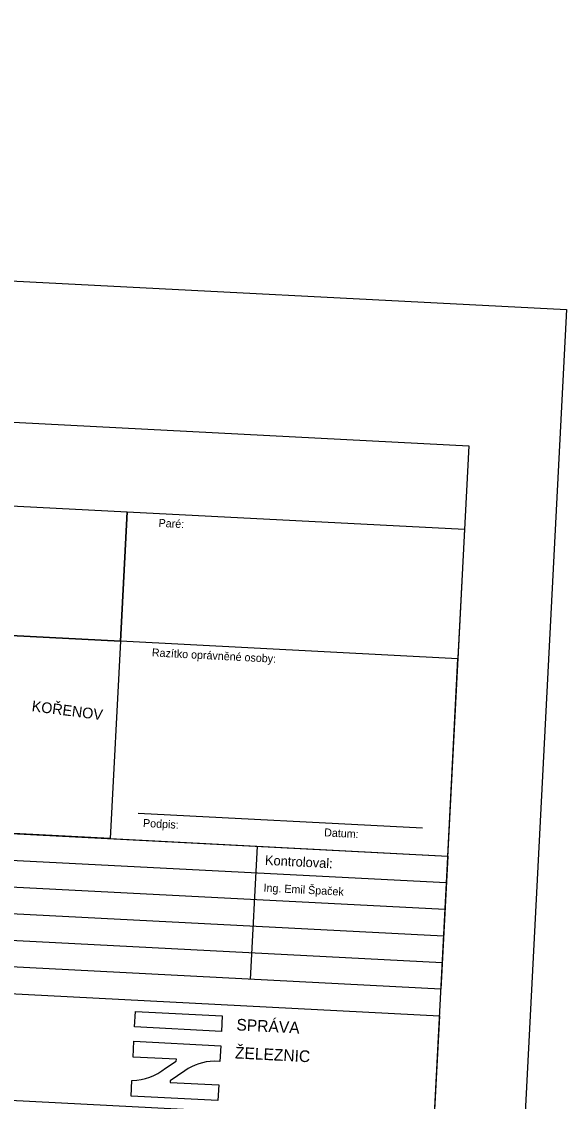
# Model space of a CAD drawing. Extents: x -669661 to -669105, y -977202 to -977030.
# Drawn here: x -669155.8 to -669104.7, y -977131.5 to -977030.3 of the extents above; entities that cross this region are included whole.
import ezdxf

# ---------------------------------------------------------------- set-up
doc = ezdxf.new("R2010")
doc.units = 0
doc.layers.add('ROZPISKA', color=7, linetype='Continuous')
doc.layers.add('Schéma', color=7, linetype='Continuous')

msp = doc.modelspace()

# ---------------------------------------------------------------- linework, layer by layer
at = {"layer": 'Defpoints'}
for p, q in [((-669629.05, -977030.28), (-669104.74, -977057.27)), ((-669629.05, -977030.28), (-669104.74, -977057.27)), ((-669104.74, -977057.27), (-669112.17, -977201.58)), ((-669104.74, -977057.27), (-669112.17, -977201.58))]:
    msp.add_line(p, q, dxfattribs=at)
at = {"layer": 'ROZPISKA'}
for p, q in [((-669144.88, -977104.46), (-669118.24, -977105.84)), ((-669200.89, -977106.57), (-669116, -977110.96)), ((-669134.35, -977120.03), (-669133.7, -977107.54)), ((-669201.02, -977109.06), (-669116.13, -977113.46)), ((-669201.15, -977111.56), (-669116.26, -977115.96)), ((-669201.15, -977111.56), (-669116.26, -977115.96)), ((-669201.28, -977114.06), (-669116.39, -977118.45))]:
    msp.add_line(p, q, dxfattribs=at)
for points in [[(-669198.77, -977065.62), (-669113.88, -977070.02), (-669120.53, -977198.35), (-669205.41, -977193.95)], [(-669199.17, -977073.46), (-669145.92, -977076.21), (-669146.55, -977088.35), (-669199.8, -977085.6)], [(-669145.92, -977076.21), (-669114.29, -977077.85), (-669114.92, -977089.99), (-669146.55, -977088.35)], [(-669199.8, -977085.6), (-669146.55, -977088.35), (-669147.51, -977106.83), (-669200.76, -977104.07)], [(-669114.92, -977089.99), (-669146.55, -977088.35), (-669147.51, -977106.83), (-669115.87, -977108.47)], [(-669200.76, -977104.07), (-669115.87, -977108.47), (-669116.52, -977120.95), (-669201.41, -977116.55)], [(-669201.54, -977119.05), (-669116.65, -977123.45), (-669117.17, -977133.43), (-669202.05, -977129.04)], [(-669145.15, -977123.02), (-669137.01, -977123.44), (-669137.08, -977124.9), (-669145.22, -977124.48)]]:
    msp.add_lwpolyline(points, close=True, dxfattribs=at)
for points in [[(-669141.31, -977127.51), (-669145.37, -977127.3), (-669145.29, -977125.83), (-669137.15, -977126.25), (-669137.23, -977127.72), (-669137.77, -977127.69)], [(-669142.33, -977128.36), (-669141.32, -977127.68), (-669141.31, -977127.51)], [(-669140.52, -977128.59), (-669141.88, -977129.53), (-669141.89, -977129.68), (-669137.34, -977129.92), (-669137.42, -977131.38), (-669145.56, -977130.96), (-669145.48, -977129.5), (-669145.45, -977129.5)]]:
    msp.add_lwpolyline(points, dxfattribs=at)
for centre, radius, start, end in [((-669145.6, -977124.24), 5.26, 271.6368, 308.4608), ((-669137.66, -977132.71), 5.02, 91.2496, 124.8162)]:
    msp.add_arc(centre, radius, start, end, dxfattribs=at)

# ---------------------------------------------------------------- texts
for s, height, p in [('Paré:', 0.75, (-669142.99, -977077.62)), ('Razítko oprávněné osoby:', 0.75, (-669143.62, -977089.76)), ('Podpis:', 0.75, (-669144.45, -977105.74)), ('Datum:', 0.75, (-669127.47, -977106.62)), ('Kontroloval:', 0.9, (-669133.02, -977109.29)), ('Ing. Emil Špaček', 0.75, (-669133.15, -977111.8)), ('SPRÁVA', 1.092, (-669135.7, -977124.8)), ('ŽELEZNIC', 1.092, (-669135.84, -977127.43))]:
    msp.add_text(s, height=height, rotation=357.0354, dxfattribs=at).set_placement(p)
at = {"layer": 'Schéma'}
msp.add_text('KOŘENOV', height=1, rotation=352.6919, dxfattribs=at).set_placement((-669154.91, -977094.89))

doc.saveas('drawing.dxf')
